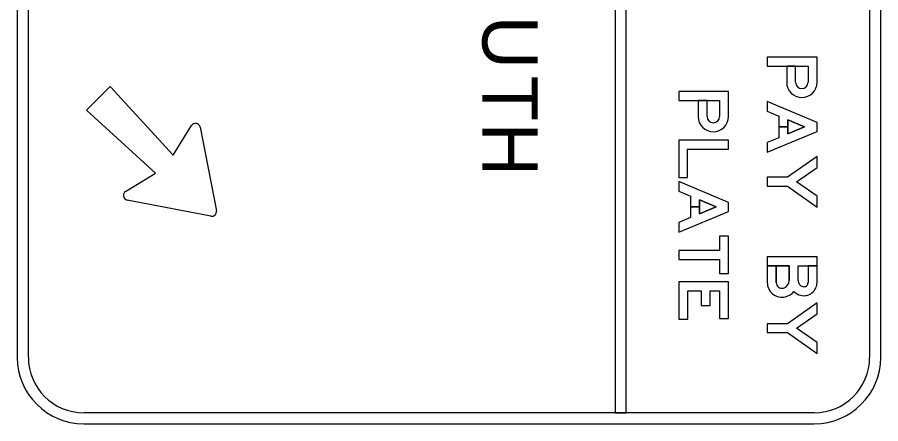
# Model space of a CAD drawing. Extents: x -830008.4 to -829992.7, y 1290284.1 to 1290294.4.
# Drawn here: x -830004.537 to -830003.757, y 1290287.657 to 1290288.025 of the extents above; entities that cross this region are included whole.
import ezdxf

# ---------------------------------------------------------------- set-up
doc = ezdxf.new("R2010")
doc.units = 0
doc.layers.add('SheetBorder_dp', color=7, linetype='Continuous')

msp = doc.modelspace()

# ---------------------------------------------------------------- linework, layer by layer
at = {"layer": 'SheetBorder_dp'}
for p, q in [((-830003.99691, 1290288.57729), (-830003.99691, 1290287.66729)), ((-830003.98691, 1290287.66729), (-830003.98691, 1290288.57729)), ((-830003.76691, 1290288.52729), (-830003.76691, 1290287.71729)), ((-830003.75691, 1290287.71729), (-830003.75691, 1290288.52729)), ((-830004.53691, 1290288.52719), (-830004.53691, 1290287.71729)), ((-830004.52691, 1290287.71729), (-830004.52691, 1290288.52719)), ((-830003.84186, 1290287.98069), (-830003.84186, 1290287.96607)), ((-830003.82251, 1290287.98069), (-830003.82251, 1290287.96607)), ((-830003.82251, 1290287.98069), (-830003.82251, 1290287.96607)), ((-830003.82251, 1290287.98069), (-830003.82251, 1290287.96607)), ((-830003.92186, 1290287.94969), (-830003.92186, 1290287.93507)), ((-830003.90251, 1290287.94969), (-830003.90251, 1290287.93507)), ((-830003.90251, 1290287.94969), (-830003.90251, 1290287.93507)), ((-830003.90251, 1290287.94969), (-830003.90251, 1290287.93507)), ((-830003.85941, 1290287.80819), (-830003.85941, 1290287.78502)), ((-830003.81691, 1290287.66729), (-830004.47691, 1290287.66729)), ((-830003.99691, 1290287.66729), (-830003.98691, 1290287.66729)), ((-830004.47691, 1290287.65729), (-830003.81691, 1290287.65729))]:
    msp.add_line(p, q, dxfattribs=at)
for points in [[(-830003.81441, 1290287.96607), (-830003.81441, 1290287.98879), (-830003.85941, 1290287.98879), (-830003.85941, 1290287.98069), (-830003.84186, 1290287.98069)], [(-830003.81441, 1290287.96607), (-830003.81441, 1290287.98879), (-830003.85941, 1290287.98879), (-830003.85941, 1290287.98069), (-830003.82251, 1290287.98069)], [(-830003.81441, 1290287.96607), (-830003.81441, 1290287.98879), (-830003.85941, 1290287.98879), (-830003.85941, 1290287.98069), (-830003.82251, 1290287.98069)], [(-830003.83376, 1290287.96607), (-830003.83376, 1290287.98069), (-830003.84186, 1290287.98069), (-830003.84186, 1290287.96607)], [(-830003.83376, 1290287.96607), (-830003.83376, 1290287.98069), (-830003.84186, 1290287.98069), (-830003.84186, 1290287.96607)], [(-830003.83376, 1290287.96607), (-830003.83376, 1290287.98069), (-830003.82251, 1290287.98069)], [(-830004.43903, 1290287.86742), (-830004.41217, 1290287.88388), (-830004.47437, 1290287.94085), (-830004.45294, 1290287.96228), (-830004.39596, 1290287.90008), (-830004.37951, 1290287.92694)], [(-830003.89441, 1290287.93507), (-830003.89441, 1290287.95779), (-830003.93941, 1290287.95779), (-830003.93941, 1290287.94969), (-830003.92186, 1290287.94969)], [(-830003.89441, 1290287.93507), (-830003.89441, 1290287.95779), (-830003.93941, 1290287.95779), (-830003.93941, 1290287.94969), (-830003.90251, 1290287.94969)], [(-830003.89441, 1290287.93507), (-830003.89441, 1290287.95779), (-830003.93941, 1290287.95779), (-830003.93941, 1290287.94969), (-830003.90251, 1290287.94969)], [(-830003.91376, 1290287.93507), (-830003.91376, 1290287.94969), (-830003.92186, 1290287.94969), (-830003.92186, 1290287.93507)], [(-830003.91376, 1290287.93507), (-830003.91376, 1290287.94969), (-830003.92186, 1290287.94969), (-830003.92186, 1290287.93507)], [(-830003.91376, 1290287.93507), (-830003.91376, 1290287.94969), (-830003.90251, 1290287.94969)], [(-830004.37169, 1290287.92553), (-830004.35703, 1290287.84994)], [(-830004.36203, 1290287.84494), (-830004.43762, 1290287.85961)], [(-830003.81441, 1290287.78502), (-830003.81441, 1290287.80819), (-830003.85941, 1290287.80819)], [(-830003.83151, 1290287.78676), (-830003.83151, 1290287.80009), (-830003.81441, 1290287.80009), (-830003.81441, 1290287.80819), (-830003.85941, 1290287.80819), (-830003.85941, 1290287.80009)], [(-830003.83151, 1290287.78676), (-830003.83151, 1290287.80009), (-830003.81441, 1290287.80009), (-830003.81441, 1290287.80819), (-830003.85941, 1290287.80819), (-830003.85941, 1290287.80009)], [(-830003.85941, 1290287.80009), (-830003.83961, 1290287.80009), (-830003.83961, 1290287.78676)], [(-830003.85131, 1290287.78502), (-830003.85131, 1290287.80009), (-830003.85941, 1290287.80009), (-830003.85941, 1290287.78502)], [(-830003.85941, 1290287.80009), (-830003.83961, 1290287.80009), (-830003.83961, 1290287.78676)], [(-830003.85131, 1290287.78502), (-830003.85131, 1290287.80009), (-830003.85941, 1290287.80009), (-830003.85941, 1290287.78502)], [(-830003.83961, 1290287.78676), (-830003.83961, 1290287.80009), (-830003.85131, 1290287.80009), (-830003.85131, 1290287.78502)], [(-830003.83151, 1290287.78676), (-830003.83151, 1290287.80009), (-830003.82251, 1290287.80009), (-830003.82251, 1290287.78502)], [(-830003.81441, 1290287.78502), (-830003.81441, 1290287.80009), (-830003.82251, 1290287.80009), (-830003.82251, 1290287.78502)], [(-830003.81441, 1290287.78502), (-830003.81441, 1290287.80009), (-830003.82251, 1290287.80009), (-830003.82251, 1290287.78502)]]:
    msp.add_lwpolyline(points, dxfattribs=at)
for points in [[(-830003.84884, 1290287.93544), (-830003.84884, 1290287.91599), (-830003.85941, 1290287.91155), (-830003.85941, 1290287.90277), (-830003.81441, 1290287.92167), (-830003.81441, 1290287.92977), (-830003.85941, 1290287.94867), (-830003.85941, 1290287.93988)], [(-830003.84074, 1290287.9194), (-830003.84074, 1290287.92571), (-830003.84884, 1290287.92571), (-830003.84884, 1290287.91599), (-830003.85941, 1290287.91155), (-830003.85941, 1290287.90277), (-830003.81441, 1290287.92167), (-830003.81441, 1290287.92977), (-830003.85941, 1290287.94867), (-830003.85941, 1290287.93988), (-830003.84884, 1290287.93544), (-830003.84884, 1290287.92572), (-830003.84074, 1290287.92572), (-830003.84074, 1290287.93204), (-830003.82569, 1290287.92572)], [(-830003.84074, 1290287.9194), (-830003.84074, 1290287.92571), (-830003.84884, 1290287.92571), (-830003.84884, 1290287.91599), (-830003.85941, 1290287.91155), (-830003.85941, 1290287.90277), (-830003.81441, 1290287.92167), (-830003.81441, 1290287.92977), (-830003.85941, 1290287.94867), (-830003.85941, 1290287.93988), (-830003.84884, 1290287.93544), (-830003.84884, 1290287.92572), (-830003.84074, 1290287.92572), (-830003.84074, 1290287.93204), (-830003.82569, 1290287.92572)], [(-830003.84074, 1290287.9194), (-830003.82569, 1290287.92572), (-830003.84074, 1290287.93204)], [(-830003.93941, 1290287.87998), (-830003.93154, 1290287.87998), (-830003.93154, 1290287.90563), (-830003.89441, 1290287.90563), (-830003.89441, 1290287.91372), (-830003.93941, 1290287.91372)], [(-830003.93941, 1290287.87998), (-830003.93154, 1290287.87998), (-830003.93154, 1290287.90563), (-830003.89441, 1290287.90563), (-830003.89441, 1290287.91372), (-830003.93941, 1290287.91372)], [(-830003.93941, 1290287.87998), (-830003.93154, 1290287.87998), (-830003.93154, 1290287.90563), (-830003.89441, 1290287.90563), (-830003.89441, 1290287.91372), (-830003.93941, 1290287.91372)], [(-830003.84119, 1290287.87209), (-830003.81441, 1290287.85319), (-830003.81441, 1290287.86311), (-830003.83288, 1290287.87614), (-830003.81441, 1290287.88918), (-830003.81441, 1290287.89909), (-830003.84119, 1290287.88019), (-830003.85941, 1290287.88019), (-830003.85941, 1290287.87209)], [(-830003.84119, 1290287.87209), (-830003.81441, 1290287.85319), (-830003.81441, 1290287.86311), (-830003.83288, 1290287.87614), (-830003.81441, 1290287.88918), (-830003.81441, 1290287.89909), (-830003.84119, 1290287.88019), (-830003.85941, 1290287.88019), (-830003.85941, 1290287.87209)], [(-830003.84119, 1290287.87209), (-830003.81441, 1290287.85319), (-830003.81441, 1290287.86311), (-830003.83288, 1290287.87614), (-830003.81441, 1290287.88918), (-830003.81441, 1290287.89909), (-830003.84119, 1290287.88019), (-830003.85941, 1290287.88019), (-830003.85941, 1290287.87209)], [(-830003.92884, 1290287.86316), (-830003.92884, 1290287.84372), (-830003.93941, 1290287.83928), (-830003.93941, 1290287.83049), (-830003.89441, 1290287.84939), (-830003.89441, 1290287.85749), (-830003.93941, 1290287.87639), (-830003.93941, 1290287.86761)], [(-830003.92074, 1290287.84712), (-830003.92074, 1290287.85344), (-830003.92884, 1290287.85344), (-830003.92884, 1290287.84372), (-830003.93941, 1290287.83928), (-830003.93941, 1290287.83049), (-830003.89441, 1290287.84939), (-830003.89441, 1290287.85749), (-830003.93941, 1290287.87639), (-830003.93941, 1290287.86761), (-830003.92884, 1290287.86316), (-830003.92884, 1290287.85344), (-830003.92074, 1290287.85344), (-830003.92074, 1290287.85976), (-830003.90569, 1290287.85344)], [(-830003.92074, 1290287.84712), (-830003.92074, 1290287.85344), (-830003.92884, 1290287.85344), (-830003.92884, 1290287.84372), (-830003.93941, 1290287.83928), (-830003.93941, 1290287.83049), (-830003.89441, 1290287.84939), (-830003.89441, 1290287.85749), (-830003.93941, 1290287.87639), (-830003.93941, 1290287.86761), (-830003.92884, 1290287.86316), (-830003.92884, 1290287.85344), (-830003.92074, 1290287.85344), (-830003.92074, 1290287.85976), (-830003.90569, 1290287.85344)], [(-830003.92074, 1290287.84712), (-830003.90569, 1290287.85344), (-830003.92074, 1290287.85976)], [(-830003.90251, 1290287.82691), (-830003.90251, 1290287.81408), (-830003.93941, 1290287.81408), (-830003.93941, 1290287.80598), (-830003.90251, 1290287.80598), (-830003.90251, 1290287.79316), (-830003.89441, 1290287.79316), (-830003.89441, 1290287.82691)], [(-830003.90251, 1290287.82691), (-830003.90251, 1290287.81408), (-830003.93941, 1290287.81408), (-830003.93941, 1290287.80598), (-830003.90251, 1290287.80598), (-830003.90251, 1290287.79316), (-830003.89441, 1290287.79316), (-830003.89441, 1290287.82691)], [(-830003.90251, 1290287.82691), (-830003.90251, 1290287.81408), (-830003.93941, 1290287.81408), (-830003.93941, 1290287.80598), (-830003.90251, 1290287.80598), (-830003.90251, 1290287.79316), (-830003.89441, 1290287.79316), (-830003.89441, 1290287.82691)], [(-830003.93131, 1290287.75179), (-830003.93131, 1290287.77744), (-830003.91921, 1290287.77744), (-830003.91921, 1290287.76417), (-830003.91111, 1290287.76417), (-830003.91111, 1290287.77744), (-830003.90251, 1290287.77744), (-830003.90251, 1290287.75247), (-830003.89441, 1290287.75247), (-830003.89441, 1290287.78554), (-830003.93941, 1290287.78554), (-830003.93941, 1290287.75179)], [(-830003.93131, 1290287.75179), (-830003.93131, 1290287.77744), (-830003.91921, 1290287.77744), (-830003.91921, 1290287.76417), (-830003.91111, 1290287.76417), (-830003.91111, 1290287.77744), (-830003.90251, 1290287.77744), (-830003.90251, 1290287.75247), (-830003.89441, 1290287.75247), (-830003.89441, 1290287.78554), (-830003.93941, 1290287.78554), (-830003.93941, 1290287.75179)], [(-830003.93131, 1290287.75179), (-830003.93131, 1290287.77744), (-830003.91921, 1290287.77744), (-830003.91921, 1290287.76417), (-830003.91111, 1290287.76417), (-830003.91111, 1290287.77744), (-830003.90251, 1290287.77744), (-830003.90251, 1290287.75247), (-830003.89441, 1290287.75247), (-830003.89441, 1290287.78554), (-830003.93941, 1290287.78554), (-830003.93941, 1290287.75179)], [(-830003.84119, 1290287.73969), (-830003.81441, 1290287.72079), (-830003.81441, 1290287.73071), (-830003.83288, 1290287.74374), (-830003.81441, 1290287.75678), (-830003.81441, 1290287.76669), (-830003.84119, 1290287.74779), (-830003.85941, 1290287.74779), (-830003.85941, 1290287.73969)], [(-830003.84119, 1290287.73969), (-830003.81441, 1290287.72079), (-830003.81441, 1290287.73071), (-830003.83288, 1290287.74374), (-830003.81441, 1290287.75678), (-830003.81441, 1290287.76669), (-830003.84119, 1290287.74779), (-830003.85941, 1290287.74779), (-830003.85941, 1290287.73969)], [(-830003.84119, 1290287.73969), (-830003.81441, 1290287.72079), (-830003.81441, 1290287.73071), (-830003.83288, 1290287.74374), (-830003.81441, 1290287.75678), (-830003.81441, 1290287.76669), (-830003.84119, 1290287.74779), (-830003.85941, 1290287.74779), (-830003.85941, 1290287.73969)]]:
    msp.add_lwpolyline(points, close=True, dxfattribs=at)
for centre, radius, start, end in [((-830004.37588, 1290287.92472), 0.00426, 10.97773, 148.51547), ((-830004.43681, 1290287.86379), 0.00426, 121.48453, 259.02227), ((-830004.36121, 1290287.84913), 0.00426, 259.02227, 10.97773), ((-830004.47691, 1290287.71729), 0.06, 180, 270), ((-830004.47691, 1290287.71729), 0.05, 180, 270), ((-830003.81691, 1290287.71729), 0.06, 270, 0), ((-830003.81691, 1290287.71729), 0.05, 270, 0)]:
    msp.add_arc(centre, radius, start, end, dxfattribs=at)
for centre, major_axis, ratio, start_param, end_param in [((-830003.82814, 1290287.96607), (0.01373, 0), 0.999995, 3.141593, 6.283185), ((-830003.82814, 1290287.96607), (0.01373, 0), 0.999995, 3.141593, 6.283185), ((-830003.82814, 1290287.96607), (0.01373, 0), 0.999995, 3.141593, 6.283185), ((-830003.82814, 1290287.96607), (0.00563, 0), 0.999995, 3.141593, 6.283185), ((-830003.82814, 1290287.96607), (0.00563, 0), 0.999995, 3.141593, 6.283185), ((-830003.82814, 1290287.96607), (0.00563, 0), 0.999995, 3.141593, 6.283185), ((-830003.90814, 1290287.93507), (0.01373, 0), 0.999995, 3.141593, 6.283185), ((-830003.90814, 1290287.93507), (0.01373, 0), 0.999995, 3.141593, 6.283185), ((-830003.90814, 1290287.93507), (0.01373, 0), 0.999995, 3.141593, 6.283185), ((-830003.90814, 1290287.93507), (0.00563, 0), 0.999995, 3.141593, 6.283185), ((-830003.90814, 1290287.93507), (0.00563, 0), 0.999995, 3.141593, 6.283185), ((-830003.90814, 1290287.93507), (0.00563, 0), 0.999995, 3.141593, 6.283185), ((-830003.84659, 1290287.78676), (0.00698, 0), 0.999999, 4.965069, 6.283185), ((-830003.84659, 1290287.78676), (0.00698, 0), 0.999999, 4.965069, 6.283185), ((-830003.84659, 1290287.78676), (0.00698, 0), 0.999999, 4.965069, 6.283185), ((-830003.82589, 1290287.78676), (0.00563, 0), 0.999999, 3.141593, 4.459709), ((-830003.82589, 1290287.78676), (0.00563, 0), 0.999999, 3.141593, 4.459709), ((-830003.82589, 1290287.78676), (0.00563, 0), 0.999999, 3.141593, 4.459709), ((-830003.84614, 1290287.78502), (0.01328, 0), 0.999999, 3.141593, 4.965069), ((-830003.84614, 1290287.78502), (0.01328, 0), 0.999999, 3.141593, 4.965069), ((-830003.84614, 1290287.78502), (0.01328, 0), 0.999999, 3.141593, 4.965069), ((-830003.84614, 1290287.78502), (0.00518, 0), 0.999999, 3.141593, 4.965069), ((-830003.84614, 1290287.78502), (0.00518, 0), 0.999999, 3.141593, 4.965069), ((-830003.84614, 1290287.78502), (0.00518, 0), 0.999999, 3.141593, 4.965069), ((-830003.82634, 1290287.78502), (0.01193, 0), 0.999999, 4.459709, 6.283185), ((-830003.82634, 1290287.78502), (0.01193, 0), 0.999999, 4.459709, 6.283185), ((-830003.82634, 1290287.78502), (0.01193, 0), 0.999999, 4.459709, 6.283185), ((-830003.82634, 1290287.78502), (0.00383, 0), 0.999999, 4.459709, 6.283185), ((-830003.82634, 1290287.78502), (0.00383, 0), 0.999999, 4.459709, 6.283185), ((-830003.82634, 1290287.78502), (0.00383, 0), 0.999999, 4.459709, 6.283185), ((-830003.84659, 1290287.78676), (0.01508, 0), 0.999999, 4.965069, 5.558736), ((-830003.84659, 1290287.78676), (0.01508, 0), 0.999999, 4.965069, 5.558736), ((-830003.84659, 1290287.78676), (0.01508, 0), 0.999999, 4.965069, 5.558736), ((-830003.82589, 1290287.78676), (0.01373, 0), 0.999999, 3.95686, 4.459709), ((-830003.82589, 1290287.78676), (0.01373, 0), 0.999999, 3.95686, 4.459709), ((-830003.82589, 1290287.78676), (0.01373, 0), 0.999999, 3.95686, 4.459709)]:
    msp.add_ellipse(centre, major_axis=major_axis, ratio=ratio, start_param=start_param, end_param=end_param, dxfattribs=at)

# ---------------------------------------------------------------- texts
for s, p in [('U', (-830004.11674, 1290288.02631)), ('T', (-830004.11674, 1290287.97196)), ('H', (-830004.11674, 1290287.92951))]:
    msp.add_text(s, height=0.05, rotation=270, dxfattribs=at).set_placement(p)

doc.saveas('drawing.dxf')
